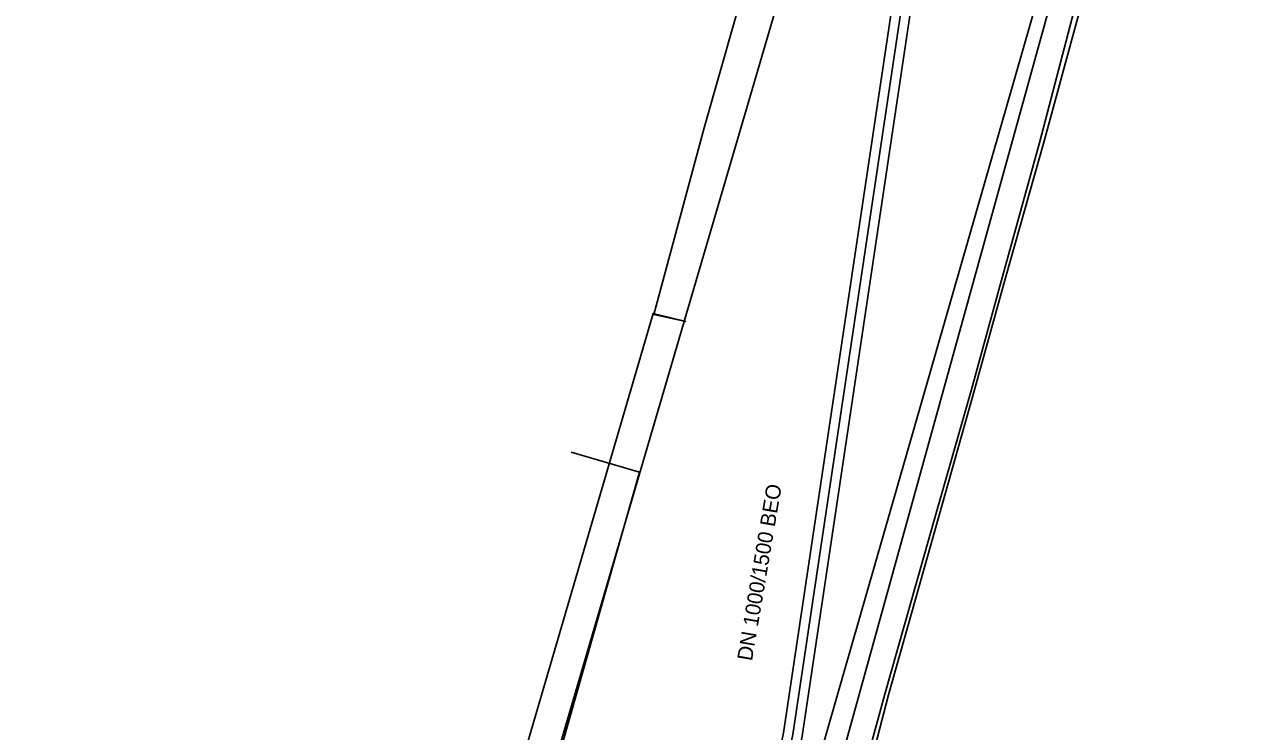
# Model space of a CAD drawing. Extents: x -600309 to -598967, y -1161267 to -1160292.
# Drawn here: x -599076.1 to -599010.8, y -1161109.2 to -1161071.8 of the extents above; entities that cross this region are included whole.
import ezdxf

# ---------------------------------------------------------------- set-up
doc = ezdxf.new("R2010")
doc.units = 0
for name, color, linetype in [('Vrstva 10', 7, 'Continuous'), ('Vrstva 12', 7, 'Continuous'), ('Vrstva 13', 7, 'Continuous'), ('Vrstva 16', 7, 'Continuous'), ('Vrstva 44', 7, 'Continuous'), ('Vrstva 55', 7, 'Continuous'), ('Vrstva 9', 7, 'Continuous')]:
    doc.layers.add(name, color=color, linetype=linetype)

msp = doc.modelspace()

# ---------------------------------------------------------------- linework, layer by layer
at = {"layer": 'Vrstva 10'}
for points in [[(-599038.27, -1161116.958), (-599036.886, -1161113.177), (-599036.39, -1161111.342), (-599035.966, -1161109.291), (-599029.238, -1161064.335)], [(-599028.249, -1161064.483), (-599034.981, -1161109.466), (-599035.417, -1161111.574), (-599035.932, -1161113.48), (-599037.33, -1161117.302)]]:
    msp.add_lwpolyline(points, dxfattribs=at)
at = {"layer": 'Vrstva 12'}
for points in [[(-599033.72, -1161061.41), (-599035.83, -1161069.1), (-599048.09, -1161110.94), (-599050.23, -1161118.09), (-599051.8, -1161121.22)], [(-599070.3, -1161155.45), (-599072.45, -1161151.38), (-599068.66, -1161148.7), (-599065.21, -1161147.1), (-599049.37, -1161115.87), (-599043.59, -1161095.5), (-599047.2, -1161094.44)]]:
    msp.add_lwpolyline(points, dxfattribs=at)
at = {"layer": 'Vrstva 13'}
msp.add_lwpolyline([(-599091.258, -1161174.108), (-599085.288, -1161172.173), (-599055.482, -1161156.208), (-599051.62, -1161150.582), (-599041.338, -1161129.035), (-599039.373, -1161124.917), (-599038.336, -1161122.744), (-599033.329, -1161112.25), (-599021.875, -1161070.87), (-599017.61, -1161055.464), (-599018.718, -1161052.521), (-599018.633, -1161052.104)], dxfattribs=at)
at = {"layer": 'Vrstva 16'}
msp.add_lwpolyline([(-599077.39, -1161169.24), (-599071.31, -1161165.62), (-599056.37, -1161155.97), (-599054.79, -1161154.77), (-599054.54, -1161154.38), (-599051.01, -1161147.09), (-599050.46, -1161145.81), (-599049.89, -1161144.61), (-599043.37, -1161131.63), (-599041.62, -1161128), (-599035.25, -1161114.76), (-599020.81, -1161064.49), (-599019.89, -1161061.02), (-599019.87, -1161060.958), (-599019.47, -1161059.72)], dxfattribs=at)
at = {"layer": 'Vrstva 44'}
for points in [[(-599031.96, -1161113.26), (-599030.4, -1161107.29), (-599027.74, -1161097.85), (-599025.85, -1161091.15), (-599024.2, -1161085.21), (-599022.2, -1161078.1), (-599020.38, -1161071.44), (-599019.891, -1161069.854), (-599019.48, -1161068.4), (-599019, -1161066.81), (-599018.43, -1161065.44), (-599018.3, -1161065.17), (-599017.79, -1161064.42), (-599017.71, -1161064.26), (-599016.03, -1161058.07), (-599016.02, -1161057.82), (-599016.03, -1161056.31), (-599015.95, -1161056.05), (-599015.6, -1161054.96), (-599015.427, -1161054.6), (-599014.846, -1161054.16), (-599011.97, -1161052.57), (-599009.122, -1161051.307)], [(-599032.2, -1161113.12), (-599030.6, -1161107.26), (-599027.92, -1161097.8), (-599026.01, -1161091.12), (-599024.37, -1161085.15), (-599022.4, -1161078.07), (-599020.59, -1161071.12)]]:
    msp.add_lwpolyline(points, dxfattribs=at)
at = {"layer": 'Vrstva 55'}
msp.add_lwpolyline([(-599078.7, -1161148.45), (-599072.64, -1161147.58), (-599065.26, -1161146.54), (-599065.56, -1161144.83), (-599051.28, -1161115.77), (-599049.63, -1161116.24), (-599051.27, -1161115.81), (-599042.87, -1161087.1), (-599041.14, -1161087.53), (-599042.83, -1161087.15), (-599040.17, -1161077.28), (-599036.84, -1161065.61), (-599036.45, -1161065.11), (-599036.22, -1161064.38), (-599036.76, -1161064.15), (-599037.05, -1161063.75)], dxfattribs=at)
at = {"layer": 'Vrstva 9'}
msp.add_lwpolyline([(-599028.744, -1161064.409), (-599035.473, -1161109.379), (-599035.903, -1161111.458), (-599036.409, -1161113.329), (-599037.8, -1161117.13)], dxfattribs=at)

# ---------------------------------------------------------------- texts
at = {"layer": 'Vrstva 12'}
msp.add_text('DN 1000/1500 BEO', height=0.8, rotation=80.35301, dxfattribs=at).set_placement((-599037.635, -1161105.527))

doc.saveas('drawing.dxf')
